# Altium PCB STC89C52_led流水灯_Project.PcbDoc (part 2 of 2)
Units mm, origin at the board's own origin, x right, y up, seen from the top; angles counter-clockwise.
Board outline 100 x 80 mm, 2 copper layers (Top Layer, Bottom Layer); 175 components, 183 nets, 540 pads, 112 vias.
Unrouted connection lines stored in the file: 28.
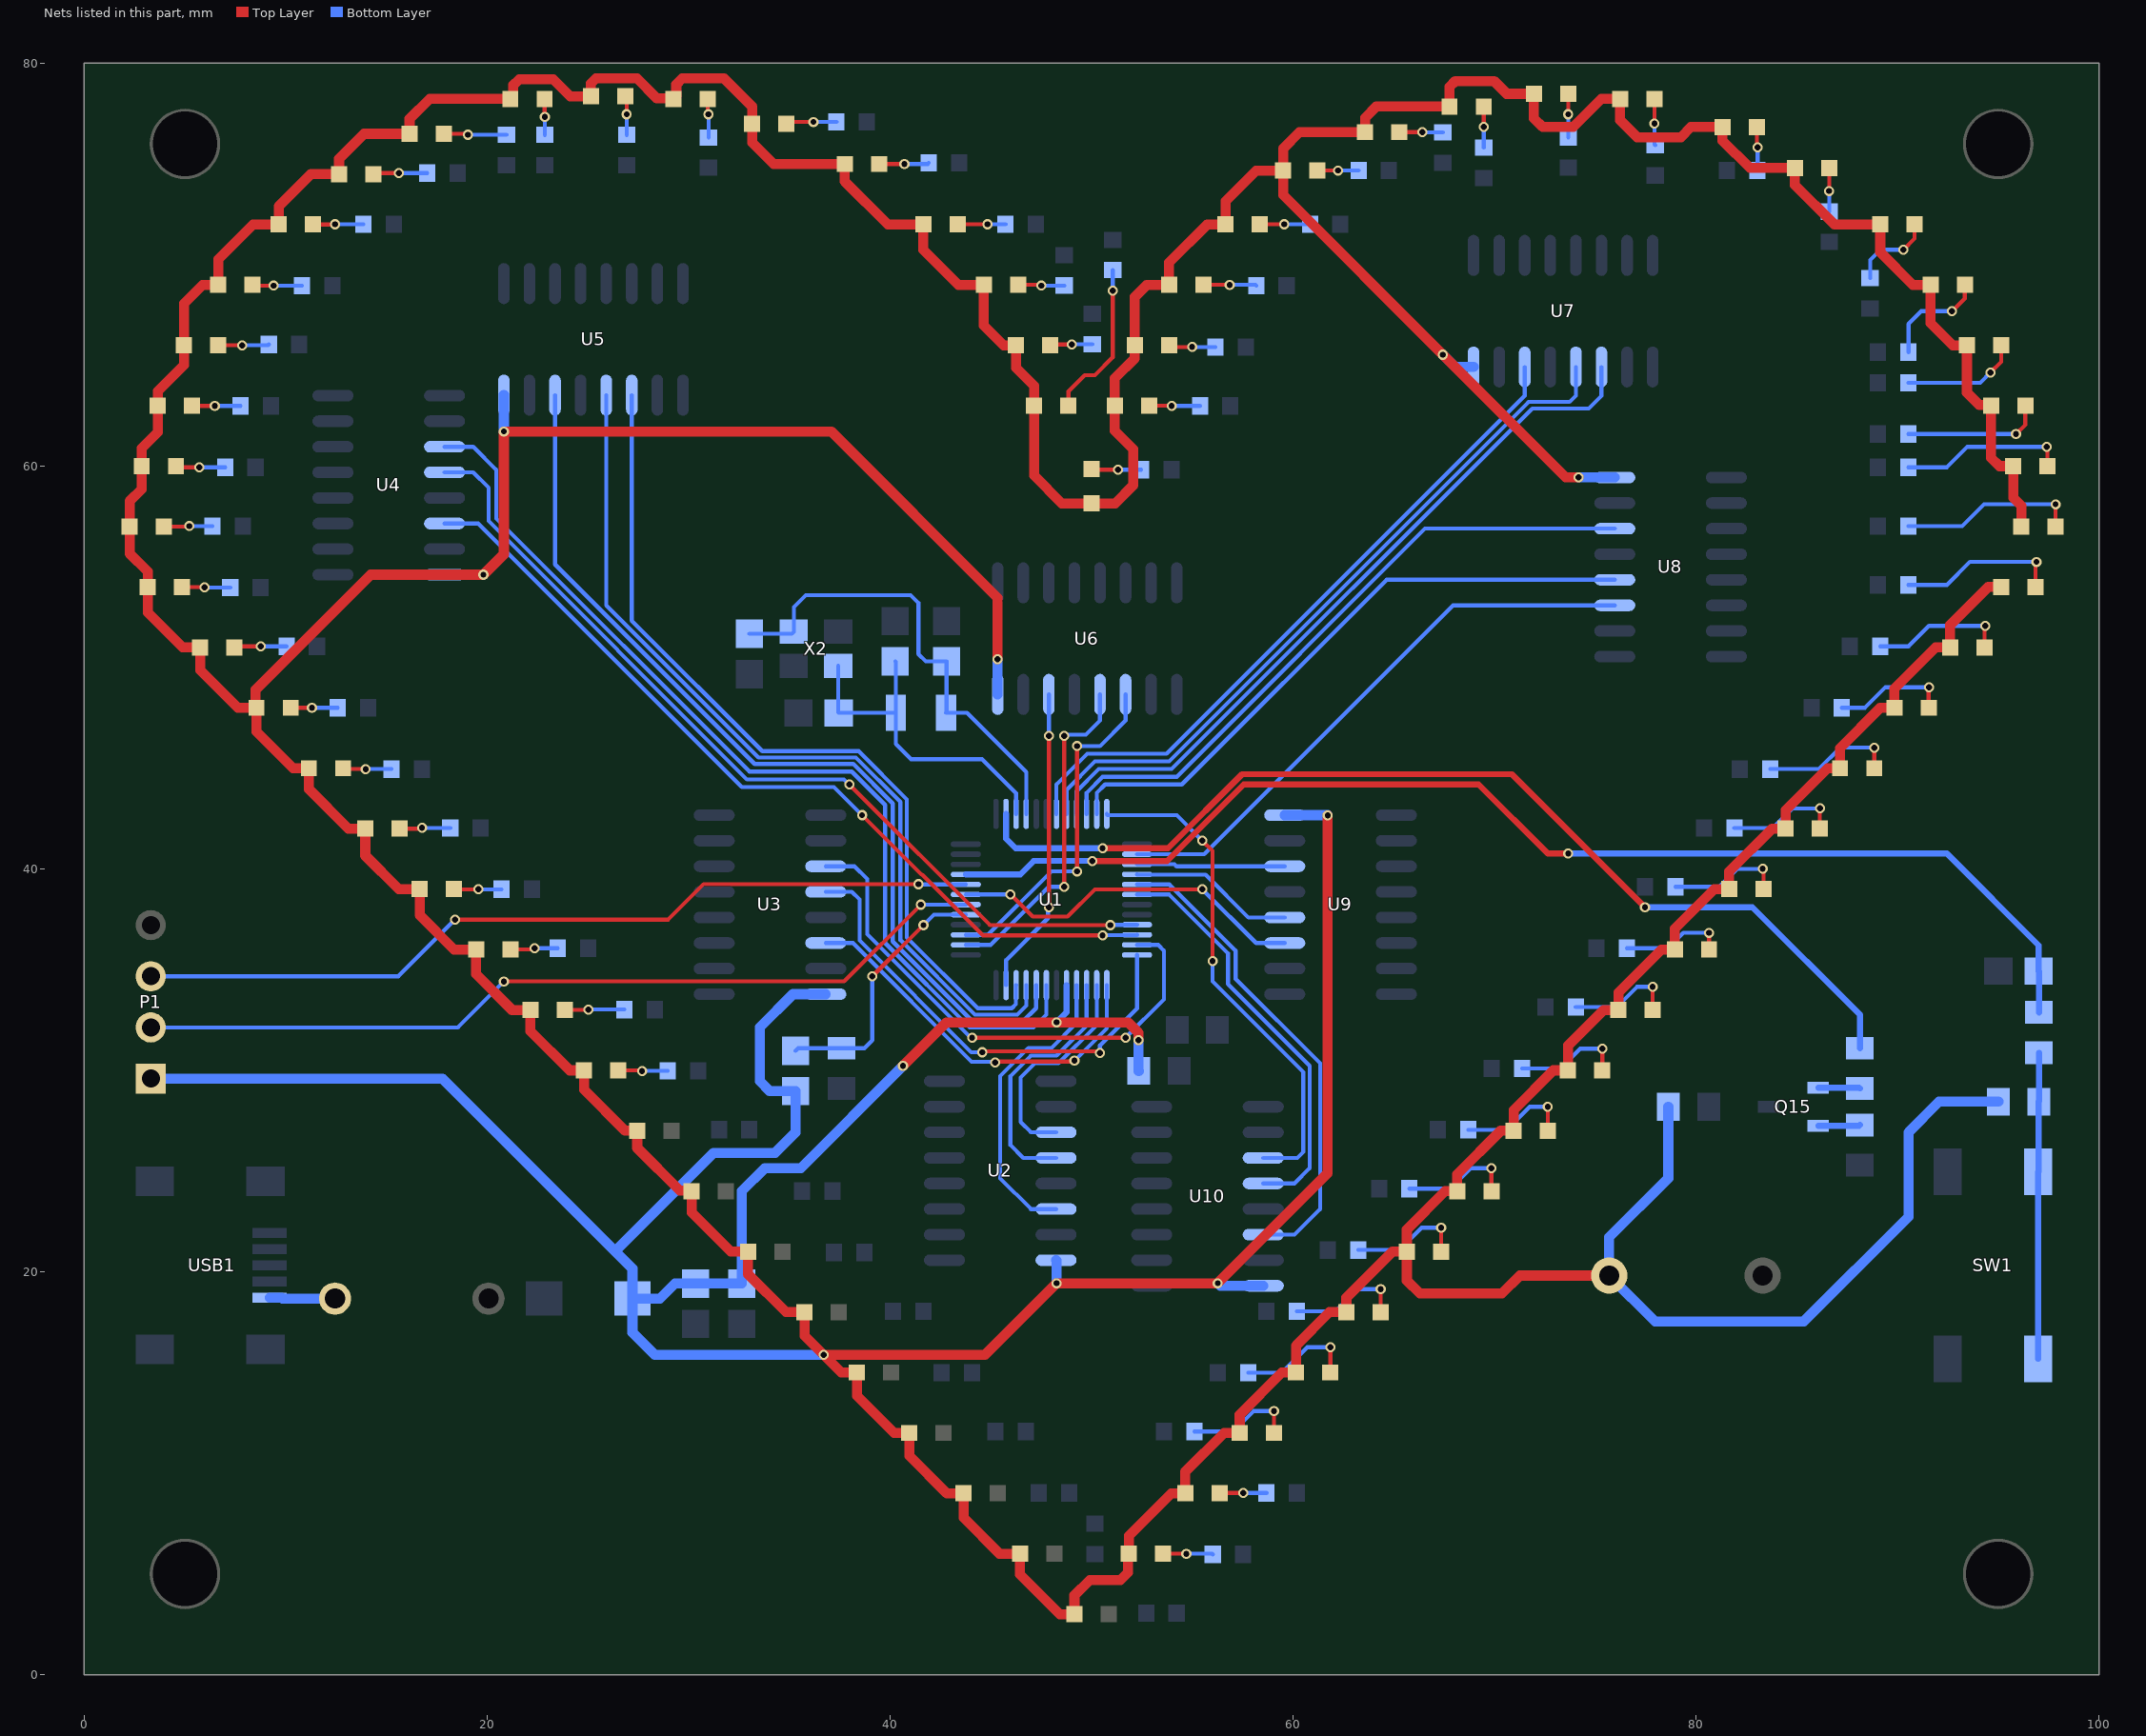
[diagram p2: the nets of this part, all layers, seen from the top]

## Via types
v1: diameter 0.5, hole 0.3, Top Layer to Bottom Layer, tented both sides, 112 vias

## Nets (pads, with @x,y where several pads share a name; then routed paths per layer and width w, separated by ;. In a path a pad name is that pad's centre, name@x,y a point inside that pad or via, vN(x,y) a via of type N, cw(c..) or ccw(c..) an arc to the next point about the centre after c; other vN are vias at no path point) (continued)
NetLED10_2: LED10.2 R10.2 | length 2.5
  Top Layer w0.2: LED10.2@26.505,30 27.658,30 v1(27.686,29.972)
  Bottom Layer w0.2: v1(27.686,29.972) R10.2@28.965,29.972
NetLED11_2: LED11.2 R11.2 | length 3
  Top Layer w0.2: LED11.2@23.851,33 24.999,33 v1(25.019,33.02)
  Bottom Layer w0.2: v1(25.019,33.02) R11.2@26.806,33.02
NetLED12_2: LED12.2 R12.2 | length 2.4
  Top Layer w0.2: LED12.2@21.151,36 22.293,36 v1(22.352,36.059)
  Bottom Layer w0.2: v1(22.352,36.059) 23.495,36.059 R12.2@23.504,36.068
NetLED13_2: LED13.2 R13.2 | length 2.4
  Top Layer w0.2: LED13.2@18.351,39 18.362,38.989 v1(19.558,38.989)
  Bottom Layer w0.2: v1(19.558,38.989) R13.2@20.71,38.989
NetLED14_2: LED14.2 R14.2 | length 2.5
  Top Layer w0.2: LED14.2@15.651,42 16.727,42 v1(16.764,42.037)
  Bottom Layer w0.2: v1(16.764,42.037) R14.2@18.17,42.037
NetLED15_2: LED15.2 R15.2 | length 2.4
  Top Layer w0.2: LED15.2@12.851,45 12.893,44.958 v1(13.97,44.958)
  Bottom Layer w0.2: v1(13.97,44.958) R15.2@15.249,44.958
NetLED16_2: LED16.2 R16.2 | length 2.3
  Top Layer w0.2: LED16.2@10.251,48 11.297,48 v1(11.303,48.006)
  Bottom Layer w0.2: v1(11.303,48.006) R16.2@12.582,48.006
NetLED17_2: LED17.2 R17.2 | length 2.6
  Top Layer w0.2: LED17.2@7.451,51 7.505,51.054 v1(8.763,51.054)
  Bottom Layer w0.2: v1(8.763,51.054) R17.2@10.042,51.054
NetLED18_2: LED18.2 R18.2 | length 2.4
  Top Layer w0.2: LED18.2@4.851,54 5.944,54 v1(5.969,53.975)
  Bottom Layer w0.2: v1(5.969,53.975) R18.2@7.248,53.975
NetLED19_2: LED19.2 R19.2 | length 2.4
  Top Layer w0.2: LED19.2@3.951,57 5.184,57 v1(5.207,57.023)
  Bottom Layer w0.2: v1(5.207,57.023) R19.2@6.359,57.023
NetLED20_2: LED20.2 R20.2 | length 2.5
  Top Layer w0.2: LED20.2@4.551,60 4.607,59.944 v1(5.715,59.944)
  Bottom Layer w0.2: v1(5.715,59.944) R20.2@6.994,59.944
NetLED21_2: LED21.2 R21.2 | length 2.4
  Top Layer w0.2: LED21.2@5.351,63 5.359,62.992 v1(6.477,62.992)
  Bottom Layer w0.2: v1(6.477,62.992) R21.2@7.756,62.992
NetLED22_2: LED22.2 R22.2 | length 2.5
  Top Layer w0.2: LED22.2@6.651,66 v1(7.834,66)
  Bottom Layer w0.2: v1(7.834,66) 9.121,66 R22.2@9.161,66.04
NetLED23_2: LED23.2 R23.2 | length 2.5
  Top Layer w0.2: LED23.2@8.351,69 8.39,68.961 v1(9.398,68.961)
  Bottom Layer w0.2: v1(9.398,68.961) R23.2@10.804,68.961
NetLED24_2: LED24.2 R24.2 | length 2.5
  Top Layer w0.2: LED24.2@11.351,72 12.437,72 v1(12.446,72.009)
  Bottom Layer w0.2: v1(12.446,72.009) R24.2@13.852,72.009
NetLED25_2: LED25.2 R25.2 | length 2.7
  Top Layer w0.2: LED25.2@14.351,74.5 14.4,74.549 v1(15.621,74.549)
  Bottom Layer w0.2: v1(15.621,74.549) R25.2@17.027,74.549
NetLED26_2: LED26.2 R26.2 | length 3.1
  Top Layer w0.2: LED26.2@17.851,76.5 19.004,76.5 v1(19.05,76.454)
  Bottom Layer w0.2: v1(19.05,76.454) R26.2@20.955,76.454
NetLED27_2: LED27.2 R27.2 | length 1.8
  Top Layer w0.2: LED27.2@22.851,78.232 22.851,77.352 v1(22.86,77.343)
  Bottom Layer w0.2: R27.2@22.86,76.445 v1(22.86,77.343)
NetLED28_2: LED28.2 R28.2 | length 1.9
  Top Layer w0.2: LED28.2@26.851,78.359 26.924,78.286 v1(26.924,77.47)
  Bottom Layer w0.2: R28.2@26.924,76.445 v1(26.924,77.47)
NetLED29_2: LED29.2 R29.2 | length 1.9
  Top Layer w0.2: LED29.2@30.95,78.232 30.95,77.508 v1(30.988,77.47)
  Bottom Layer w0.2: R29.2@30.988,76.318 v1(30.988,77.47)
NetLED30_2: LED30.2 R30.2 | length 2.5
  Top Layer w0.2: LED30.2@34.851,77 34.94,77.089 v1(36.195,77.089)
  Bottom Layer w0.2: v1(36.195,77.089) R30.2@37.338,77.089
NetLED31_2: LED31.2 R31.2 | length 2.5
  Top Layer w0.2: LED31.2@39.451,75 v1(40.71,75)
  Bottom Layer w0.2: v1(40.71,75) 41.862,75 R31.2@41.919,75.057
NetLED32_2: LED32.2 R32.2 | length 2.4
  Top Layer w0.2: LED32.2@43.351,72 43.36,72.009 v1(44.831,72.009)
  Bottom Layer w0.2: v1(44.831,72.009) R32.2@45.729,72.009
NetLED33_2: LED33.2 R33.2 | length 2.3
  Top Layer w0.2: LED33.2@46.351,69 47.459,69 v1(47.498,68.961)
  Bottom Layer w0.2: v1(47.498,68.961) R33.2@48.65,68.961
NetLED34_2: LED34.2 R34.2 | length 2.1
  Top Layer w0.2: LED34.2@47.951,66 47.991,66.04 v1(49.022,66.04)
  Bottom Layer w0.2: v1(49.022,66.04) 49.031,66.049 R34.2@50.038,66.049
NetLED35_2: LED35.2 R35.2 | length 7.9
  Top Layer w0.2: LED35.2@48.851,63 48.851,63.71 49.657,64.516 50.165,64.516 51.054,65.405 v1(51.054,68.707)
  Bottom Layer w0.2: v1(51.054,68.707) R35.2@51.054,69.732
NetLED36_2: LED36.2 R36.2 | length 2.5
  Top Layer w0.2: LED36.2@50,59.851 50.034,59.817 v1(51.308,59.817)
  Bottom Layer w0.2: v1(51.308,59.817) R36.2@52.46,59.817
NetLED37_2: LED37.2 R37.2 | length 2.5
  Top Layer w0.2: LED37.2@52.851,63 53.967,63 v1(53.975,62.992)
  Bottom Layer w0.2: v1(53.975,62.992) R37.2@55.381,62.992
NetLED38_2: LED38.2 R38.2 | length 2.3
  Top Layer w0.2: LED38.2@53.851,66 53.938,65.913 v1(54.991,65.913)
  Bottom Layer w0.2: v1(54.991,65.913) R38.2@56.143,65.913
NetLED39_2: LED39.2 R39.2 | length 2.6
  Top Layer w0.2: LED39.2@55.551,69 v1(56.857,69)
  Bottom Layer w0.2: v1(56.857,69) 58.136,69 R39.2@58.175,68.961
NetLED40_2: LED40.2 R40.2 | length 2.5
  Top Layer w0.2: LED40.2@58.351,72 58.36,72.009 v1(59.563,72.009)
  Bottom Layer w0.2: v1(59.563,72.009) R40.2@60.842,72.009
NetLED41_2: LED41.2 R41.2 | length 2
  Top Layer w0.2: LED41.2@61.214,74.676 v1(62.23,74.676)
  Bottom Layer w0.2: v1(62.23,74.676) R41.2@63.255,74.676
NetLED42_2: LED42.2 R42.2 | length 2.2
  Top Layer w0.2: LED42.2@65.278,76.581 v1(66.421,76.581)
  Bottom Layer w0.2: v1(66.421,76.581) 66.43,76.572 R42.2@67.437,76.572
NetLED43_2: LED43.2 R43.2 | length 2
  Top Layer w0.2: v1(69.469,76.835) LED43.2@69.469,77.851
  Bottom Layer w0.2: R43.2@69.469,75.81 v1(69.469,76.835)
NetLED44_2: LED44.2 R44.2 | length 2.2
  Top Layer w0.2: v1(73.66,77.47) LED44.2@73.66,78.486
  Bottom Layer w0.2: R44.2@73.66,76.318 v1(73.66,77.47)
NetLED45_2: LED45.2 R45.2 | length 2.3
  Top Layer w0.2: v1(77.94,77) LED45.2@77.94,78.232
  Bottom Layer w0.2: v1(77.94,77) 77.94,75.975 R45.2@77.978,75.937
NetLED46_2: LED46.2 R46.2 | length 2.2
  Top Layer w0.2: LED46.2@83.02,76.835 83.02,75.857 v1(83.058,75.819)
  Bottom Layer w0.2: R46.2@83.049,74.676 83.058,74.685 v1(83.058,75.819)
NetLED47_2: LED47.2 R47.2 | length 2.2
  Top Layer w0.2: v1(86.614,73.66) LED47.2@86.614,74.803
  Bottom Layer w0.2: R47.2@86.614,72.635 v1(86.614,73.66)
NetLED48_2: LED48.2 R48.2 | length 4.2
  Top Layer w0.2: v1(90.297,70.739) 90.851,71.293 LED48.2@90.851,72
  Bottom Layer w0.2: R48.2@88.646,69.333 88.646,70.231 89.154,70.739 v1(90.297,70.739)
NetLED49_2: LED49.2 R49.2 | length 5.4
  Top Layer w0.2: v1(92.71,67.691) 93.345,68.326 93.345,68.994 LED49.2@93.351,69
  Bottom Layer w0.2: R49.2@90.551,65.659 90.551,67.056 91.186,67.691 v1(92.71,67.691)
NetLED50_2: LED50.2 R50.2 | length 5.9
  Top Layer w0.2: v1(94.615,64.643) 95.151,65.179 LED50.2@95.151,66
  Bottom Layer w0.2: R50.2@90.542,64.135 94.107,64.135 v1(94.615,64.643)
NetLED51_2: LED51.2 R51.2 | length 6.9
  Top Layer w0.2: v1(95.885,61.595) 96.351,62.061 LED51.2@96.351,63
  Bottom Layer w0.2: R51.2@90.542,61.595 v1(95.885,61.595)
NetLED52_2: LED52.2 R52.2 | length 8.3
  Top Layer w0.2: v1(97.409,60.96) 97.409,60.833 97.451,60.791 LED52.2@97.451,60
  Bottom Layer w0.2: R52.2@90.542,59.944 92.456,59.944 93.472,60.96 v1(97.409,60.96)
NetLED53_2: LED53.2 R53.2 | length 8.9
  Top Layer w0.2: LED53.2@97.851,57 v1(97.851,58.105)
  Bottom Layer w0.2: R53.2@90.542,57.023 93.218,57.023 94.3,58.105 v1(97.851,58.105)
NetLED54_2: LED54.2 R54.2 | length 8.1
  Top Layer w0.2: LED54.2@96.851,54 96.851,55.195 v1(96.901,55.245)
  Bottom Layer w0.2: R54.2@90.542,54.102 92.456,54.102 93.599,55.245 v1(96.901,55.245)
NetLED55_2: LED55.2 R55.2 | length 6.7
  Top Layer w0.2: LED55.2@94.323,51 94.323,52.032 v1(94.361,52.07)
  Bottom Layer w0.2: R55.2@89.145,51.054 90.551,51.054 91.567,52.07 v1(94.361,52.07)
NetLED56_2: LED56.2 R56.2 | length 5.8
  Top Layer w0.2: LED56.2@91.551,48 91.551,49.006 v1(91.567,49.022)
  Bottom Layer w0.2: R56.2@87.24,48.006 88.392,48.006 89.408,49.022 v1(91.567,49.022)
NetLED57_2: LED57.2 R57.2 | length 6.6
  Top Layer w0.2: LED57.2@88.851,45 v1(88.851,46.023)
  Bottom Layer w0.2: R57.2@83.684,44.958 86.106,44.958 87.171,46.023 v1(88.851,46.023)
NetLED58_2: LED58.2 R58.2 | length 5.7
  Top Layer w0.2: LED58.2@86.151,42 v1(86.151,43.008)
  Bottom Layer w0.2: R58.2@81.906,42.037 83.82,42.037 84.791,43.008 v1(86.151,43.008)
NetLED59_2: LED59.2 R59.2 | length 5.7
  Top Layer w0.2: v1(83.312,40.005) 83.351,39.966 LED59.2@83.351,39
  Bottom Layer w0.2: R59.2@78.985,39.116 81.153,39.116 82.042,40.005 v1(83.312,40.005)
NetLED60_2: LED60.2 R60.2 | length 5.2
  Top Layer w0.2: v1(80.645,36.83) 80.651,36.824 LED60.2@80.651,36
  Bottom Layer w0.2: R60.2@76.572,36.068 78.613,36.068 79.375,36.83 v1(80.645,36.83)
NetLED61_2: LED61.2 R61.2 | length 5.4
  Top Layer w0.2: LED61.2@77.851,33 v1(77.851,34.145)
  Bottom Layer w0.2: R61.2@74.032,33.147 76.073,33.147 77.071,34.145 v1(77.851,34.145)
NetLED62_2: LED62.2 R62.2 | length 5.5
  Top Layer w0.2: LED62.2@75.351,30 v1(75.351,31.075)
  Bottom Layer w0.2: R62.2@71.365,30.099 73.279,30.099 74.255,31.075 v1(75.351,31.075)
NetLED63_2: LED63.2 R63.2 | length 5.6
  Top Layer w0.2: v1(72.644,28.194) 72.651,28.187 LED63.2@72.651,27
  Bottom Layer w0.2: R63.2@68.698,27.051 70.612,27.051 71.755,28.194 v1(72.644,28.194)
NetLED64_2: LED64.2 R64.2 | length 5.6
  Top Layer w0.2: v1(69.85,25.146) v1(69.85,25.146) LED64.2@69.851,24
  Bottom Layer w0.2: R64.2@65.777,24.13 67.818,24.13 68.834,25.146 v1(69.85,25.146)
NetLED65_2: LED65.2 R65.2 | length 5.8
  Top Layer w0.2: LED65.2@67.351,21 v1(67.351,22.184)
  Bottom Layer w0.2: R65.2@63.237,21.082 65.278,21.082 66.38,22.184 v1(67.351,22.184)
NetLED66_2: LED66.2 R66.2 | length 5.8
  Top Layer w0.2: LED66.2@64.351,18 v1(64.351,19.139)
  Bottom Layer w0.2: R66.2@60.189,18.034 62.103,18.034 63.208,19.139 v1(64.351,19.139)
NetLED67_2: LED67.2 R67.2 | length 5.9
  Top Layer w0.2: v1(61.849,16.256) 61.851,16.254 LED67.2@61.851,15
  Bottom Layer w0.2: R67.2@57.776,14.986 59.436,14.986 60.706,16.256 v1(61.849,16.256)
NetLED68_2: LED68.2 R68.2 | length 5.4
  Top Layer w0.2: LED68.2@59.055,12 v1(59.055,13.081)
  Bottom Layer w0.2: R68.2@55.109,12.065 57.023,12.065 58.039,13.081 v1(59.055,13.081)
NetLED69_2: LED69.2 R69.2 | length 2.3
  Top Layer w0.2: LED69.2@56.351,9 56.368,9.017 v1(57.531,9.017)
  Bottom Layer w0.2: v1(57.531,9.017) R69.2@58.683,9.017
NetLED70_2: LED70.2 R70.2 | length 2.5
  Top Layer w0.2: LED70.2@53.551,6 v1(54.706,6)
  Bottom Layer w0.2: v1(54.706,6) 55.985,6 R70.2@56.016,5.969
NetQ15_1: Q15.1 R75.1 | length 2.1
  Bottom Layer w0.3: Q15.1@86.071,29.144 88.093,29.144 R75.1@88.138,29.099
NetQ15_2: Q15.2 R72.2 | length 2.1
  Bottom Layer w0.3: Q15.2@86.071,27.244 88.093,27.244 R72.2@88.138,27.289
NetR73_1: R73.1 R74.1 SW1.1 SW1.2 | length 15.2
  Bottom Layer w0.3: SW1.1@96.992,15.677 SW1.2@96.992,24.963 97.012,24.983 R73.1@97.012,28.448 97.028,28.464 R74.1@97.028,30.877
P0.0: U1.40 U2.14 | length 15.2
  Bottom Layer w0.2: U2.14@48.235,23.114 46.99,23.114 45.466,24.638 45.466,29.718 46.863,31.115 48.006,31.115 49.256,32.365 U1.40@49.256,34.231
P0.1: U1.39 U2.12 | length 12.8
  Bottom Layer w0.2: U2.12@48.235,25.654 46.609,25.654 45.974,26.289 45.974,29.718 46.99,30.734 48.26,30.734 49.756,32.23 U1.39@49.756,34.231
P0.2: U1.38 U2.11 | length 11
  Bottom Layer w0.2: U2.11@48.235,26.924 46.99,26.924 46.482,27.432 46.482,29.651 47.184,30.353 48.357,30.353 50.256,32.252 U1.38@50.256,34.231
P0.3: U1.37 U3.14 | length 19.3
  Top Layer w0.2: v1(45.212,30.391) 45.257,30.436 49.105,30.436 v1(49.149,30.48)
  Bottom Layer w0.2: U3.14@36.805,36.322 38.155,36.322 44.048,30.429 45.174,30.429 v1(45.212,30.391) ; v1(49.149,30.48) 50.756,32.087 U1.37@50.756,34.231
P0.4: U1.36 U3.12 | length 23.8
  Top Layer w0.2: v1(44.577,30.899) 44.628,30.95 50.249,30.95 50.338,30.861 v1(50.419,30.861)
  Bottom Layer w0.2: U3.12@36.805,38.862 38.1,38.862 38.481,38.481 38.481,36.449 44.027,30.903 44.573,30.903 v1(44.577,30.899) ; v1(50.419,30.861) 50.419,31.242 52.256,33.079 U1.36@52.256,35.731
P0.5: U1.35 U3.11 | length 26.6
  Top Layer w0.2: v1(44.069,31.623) v1(51.689,31.623)
  Bottom Layer w0.2: U3.11@36.805,40.132 38.227,40.132 38.862,39.497 38.862,36.758 43.997,31.623 v1(44.069,31.623) ; v1(51.689,31.623) 53.594,33.528 53.594,35.941 53.304,36.231 U1.35@52.256,36.231
P0.6: U1.34 U4.14 | length 42.9
  Top Layer w0.2: v1(38.608,42.672) 41.567,39.713 41.597,39.713 44.607,36.703 v1(50.546,36.703)
  Bottom Layer w0.2: U4.14@17.882,57.15 19.558,57.15 32.639,44.069 37.211,44.069 v1(38.608,42.672) ; v1(50.546,36.703) 50.561,36.718 52.243,36.718 U1.34@52.256,36.731
P0.7: U1.33 U4.12 | length 44.7
  Top Layer w0.2: v1(37.973,44.196) 44.958,37.211 v1(50.927,37.211)
  Bottom Layer w0.2: U4.12@17.882,59.69 19.304,59.69 20.066,58.928 20.066,57.277 32.893,44.45 37.706,44.45 37.96,44.196 v1(37.973,44.196) ; v1(50.927,37.211) 50.937,37.221 52.246,37.221 U1.33@52.256,37.231
P1.0: U1.43 U4.11 | length 49
  Bottom Layer w0.2: U4.11@17.882,60.96 19.304,60.96 20.447,59.817 20.447,57.404 33.02,44.831 38.1,44.831 39.751,43.18 39.751,36.322 43.947,32.126 47.122,32.126 47.756,32.76 U1.43@47.756,34.231
P1.1: U1.44 U5.14 | length 47.1
  Bottom Layer w0.2: U5.14@23.368,63.525 23.368,55.118 33.274,45.212 38.172,45.212 40.132,43.252 40.132,36.394 44.08,32.446 46.604,32.446 47.244,33.086 47.244,34.219 U1.44@47.256,34.231
P1.2: U1.45 U5.12 | length 44.9
  Bottom Layer w0.2: U5.12@25.908,63.525 25.908,53.086 33.462,45.532 38.304,45.532 40.513,43.323 40.513,36.465 44.212,32.766 46.306,32.766 46.756,33.216 U1.45@46.756,34.231
P1.3: U1.46 U5.11 | length 43.3
  Bottom Layer w0.2: U5.11@27.178,63.525 27.178,52.324 33.65,45.852 38.437,45.852 40.833,43.456 40.833,36.598 44.345,33.086 46.04,33.086 46.243,33.289 46.243,34.218 U1.46@46.256,34.231
P1.4: U1.47 U6.14 | length 15.3
  Top Layer w0.2: v1(47.879,38.1) v1(47.879,46.609)
  Bottom Layer w0.2: U1.47@45.756,34.231 45.756,35.469 47.837,37.55 47.837,38.058 v1(47.879,38.1) ; v1(47.879,46.609) U6.14@47.879,48.666
P1.5: U1.2 U6.12 | length 17
  Top Layer w0.2: v1(48.641,39.116) v1(48.641,46.609)
  Bottom Layer w0.2: U1.2@43.756,36.231 44.994,36.231 47.879,39.116 v1(48.641,39.116) ; v1(48.641,46.609) 48.698,46.666 49.714,46.666 50.419,47.371 U6.12@50.419,48.666
P1.6: U1.3 U6.11 | length 17.3
  Top Layer w0.2: v1(49.276,39.878) v1(49.276,46.101)
  Bottom Layer w0.2: U1.3@43.756,36.731 44.859,36.731 48.006,39.878 v1(49.276,39.878) ; v1(49.276,46.101) 50.419,46.101 51.689,47.371 U6.11@51.689,48.666
P2.0: U1.19 U7.14 | length 34.1
  Bottom Layer w0.2: U1.19@48.256,42.731 48.256,44.192 49.784,45.72 53.721,45.72 71.501,63.5 U7.14@71.501,64.922
P2.1: U1.20 U7.12 | length 36
  Bottom Layer w0.2: U1.20@48.756,42.731 48.756,43.93 50.165,45.339 53.848,45.339 71.694,63.185 73.726,63.185 74.041,63.5 U7.12@74.041,64.922
P2.2: U1.21 U7.11 | length 36.7
  Bottom Layer w0.2: U1.21@49.256,42.731 49.256,43.856 50.358,44.958 53.975,44.958 71.882,62.865 74.676,62.865 75.311,63.5 U7.11@75.311,64.922
P2.3: U1.22 U8.14 | length 32.7
  Bottom Layer w0.2: U1.22@49.756,42.731 49.756,43.787 50.546,44.577 54.229,44.577 66.548,56.896 U8.14@75.971,56.896
P2.4: U1.23 U8.12 | length 31.1
  Bottom Layer w0.2: U1.23@50.256,42.731 50.256,43.779 50.673,44.196 54.483,44.196 64.643,54.356 U8.12@75.971,54.356
P2.5: U1.26 U8.11 | length 28.8
  Bottom Layer w0.2: U1.26@52.256,40.731 55.59,40.731 67.945,53.086 U8.11@75.971,53.086
P2.6: U1.27 U9.14 | length 7.4
  Bottom Layer w0.2: U1.27@52.256,40.231 54.119,40.231 54.218,40.132 U9.14@59.588,40.132
P2.7: U1.28 U9.12 | length 8.2
  Bottom Layer w0.2: U1.28@52.256,39.731 52.269,39.718 55.659,39.718 57.785,37.592 U9.12@59.588,37.592
P3.0: P1.2 U1.6 | length 43
  Top Layer w0.2: v1(20.828,34.417) 37.719,34.417 v1(41.529,38.227)
  Bottom Layer w0.2: P1.2@3.302,32.131 18.542,32.131 v1(20.828,34.417) ; v1(41.529,38.227) 41.533,38.231 U1.6@43.756,38.231
P3.1: P1.3 U1.8 | length 42.4
  Top Layer w0.2: v1(18.403,37.487) 28.984,37.487 30.74,39.243 v1(41.402,39.243)
  Bottom Layer w0.2: P1.3@3.302,34.671 15.587,34.671 v1(18.403,37.487) ; v1(41.402,39.243) 41.414,39.231 U1.8@43.756,39.231
P3.2: C5.2 R74.2 U1.9 | length 61.8
  Top Layer w0.3: v1(50.038,40.386) 53.748,40.386 57.558,44.196 69.215,44.196 72.644,40.767 v1(73.66,40.767)
  Bottom Layer w0.3: U1.9@43.756,39.731 46.462,39.731 47.129,40.398 50.026,40.398 v1(50.038,40.386) ; v1(73.66,40.767) 92.456,40.767 97.012,36.211 C5.2@97.012,34.925 97.028,34.909 R74.2@97.028,32.877
P3.7: R75.2 U1.14 | length 52
  Top Layer w0.3: v1(50.546,41.021) 53.789,41.021 57.472,44.704 70.866,44.704 v1(77.47,38.1)
  Bottom Layer w0.3: U1.14@45.756,42.731 45.756,41.493 46.228,41.021 v1(50.546,41.021) ; v1(77.47,38.1) 82.804,38.1 88.138,32.766 R75.2@88.138,31.099
P4.3: U1.7 U9.11 | length 18
  Top Layer w0.2: v1(45.974,38.735) 47.079,37.63 48.806,37.63 50.165,38.989 v1(55.499,38.989)
  Bottom Layer w0.2: U1.7@43.756,38.731 43.758,38.733 45.972,38.733 v1(45.974,38.735) ; v1(55.499,38.989) 58.166,36.322 U9.11@59.588,36.322
P4.4: U1.29 U10.14 | length 24.2
  Bottom Layer w0.2: U1.29@52.256,39.231 53.86,39.231 57.15,35.941 57.15,34.544 61.341,30.353 61.341,23.114 60.071,21.844 U10.14@58.522,21.844
P4.5: U1.30 U10.12 | length 20.7
  Bottom Layer w0.2: U1.30@52.256,38.731 53.852,38.731 56.769,35.814 56.769,34.29 60.833,30.226 60.833,25.146 60.071,24.384 U10.12@58.522,24.384
P5.0: U1.24 U10.11 | length 24.9
  Top Layer w0.2: v1(55.499,41.402) 56.007,40.894 56.007,35.924 v1(56.007,35.433)
  Bottom Layer w0.2: U1.24@50.756,42.731 50.788,42.699 50.788,42.672 54.229,42.672 v1(55.499,41.402) ; v1(56.007,35.433) 56.007,34.417 60.513,29.911 60.513,25.959 60.208,25.654 U10.11@58.522,25.654
RST: C6.1 R71.2 U1.5 | length 13.1
  Top Layer w0.2: v1(39.116,34.671) v1(41.656,37.211)
  Bottom Layer w0.2: C6.1@35.306,30.972 35.433,31.099 R71.2@37.592,31.099 38.719,31.099 39.116,31.496 v1(39.116,34.671) ; v1(41.656,37.211) 42.176,37.731 U1.5@43.756,37.731
VBUS: SW2.1 USB1.1 | length 3.3
  Bottom Layer w0.5: USB1.1@9.2,18.72 9.8,18.72 9.851,18.669 SW2.1@12.446,18.669
VCC_5V: BUZZER2.1 C3.2 C4.2 C6.2 D1.1 LED1.1 LED2.1 LED3.1 LED4.1 LED5.1 LED6.1 LED7.1 LED8.1 LED9.1 LED10.1 LED11.1 LED12.1 LED13.1 LED14.1 LED15.1 LED16.1 LED17.1 LED18.1 LED19.1 LED20.1 LED21.1 LED22.1 LED23.1 LED24.1 LED25.1 LED26.1 LED27.1 LED28.1 LED29.1 LED30.1 LED31.1 LED32.1 LED33.1 LED34.1 LED35.1 LED36.1 LED37.1 LED38.1 LED39.1 LED40.1 LED41.1 LED42.1 LED43.1 LED44.1 LED45.1 LED46.1 LED47.1 LED48.1 LED49.1 LED50.1 LED51.1 LED52.1 LED53.1 LED54.1 LED55.1 LED56.1 LED57.1 LED58.1 LED59.1 LED60.1 LED61.1 LED62.1 LED63.1 LED64.1 LED65.1 LED66.1 LED67.1 LED68.1 LED69.1 LED70.1 P1.1 R73.2 R76.2 R78.2 U1.41 U2.16 U3.16 U4.16 U5.16 U6.16 U7.16 U8.16 U9.16 U10.16 | length 610.1
  Top Layer w0.5: v1(40.64,30.226) 42.799,32.385 v1(48.26,32.385) 51.804,32.385 52.324,31.865 v1(52.324,31.496) ; v1(45.339,50.419) 45.339,53.467 37.084,61.722 v1(20.828,61.722) 20.828,55.626 v1(19.812,54.61) 14.224,54.61 8.509,48.895 8.509,48.04 LED16.1@8.549,48 ; v1(61.722,42.66) 61.722,24.892 v1(56.261,19.431) v1(48.26,19.431) 44.704,15.875 v1(36.703,15.875) ; v1(74.168,59.436) 73.533,59.436 v1(67.437,65.532) 59.512,73.457 LED41.1@59.512,74.676 ; BUZZER2.1@75.692,19.812 71.262,19.812 70.373,18.923 66.294,18.923 65.649,19.568 LED65.1@65.649,21 ; LED54.1@95.149,54 94.513,54 92.621,52.108 LED55.1@92.621,51 91.894,51 89.849,48.955 LED56.1@89.849,48 89.148,48 87.149,46.001 LED57.1@87.149,45 86.529,45 84.449,42.92 LED58.1@84.449,42 83.783,42 81.649,39.866 LED59.1@81.649,39 80.91,39 78.949,37.039 LED60.1@78.949,36 78.291,36 76.149,33.858 LED61.1@76.149,33 75.418,33 73.649,31.231 LED62.1@73.649,30 72.926,30 70.949,28.023 LED63.1@70.949,27 70.307,27 68.149,24.842 LED64.1@68.149,24 67.561,24 65.649,22.088 LED65.1@65.649,21 ; LED53.1@96.149,57 96.149,58.029 95.749,58.429 LED52.1@95.749,60 95.067,60 94.649,60.418 LED51.1@94.649,63 94.616,63.033 94.066,63.033 93.449,63.65 LED50.1@93.449,66 92.75,66 91.649,67.101 LED49.1@91.649,69 90.766,69 89.149,70.617 LED48.1@89.149,72 86.877,72 84.912,73.965 LED47.1@84.912,74.803 82.677,74.803 81.318,76.162 LED46.1@81.318,76.835 79.756,76.835 79.248,76.327 77.089,76.327 76.238,77.178 LED45.1@76.238,78.232 75.311,78.232 73.914,76.835 72.39,76.835 71.958,77.267 LED44.1@71.958,78.486 70.612,78.486 69.977,79.121 68.06,79.121 67.767,78.828 LED43.1@67.767,77.851 64.135,77.851 63.576,77.292 LED42.1@63.576,76.581 60.325,76.581 59.512,75.768 LED41.1@59.512,74.676 ; LED16.1@8.549,48 7.626,48 5.749,49.877 LED17.1@5.749,51 4.88,51 3.149,52.731 LED18.1@3.149,54 3.149,54.763 2.249,55.663 LED19.1@2.249,57 2.249,58.256 2.849,58.856 LED20.1@2.849,60 2.849,60.888 3.649,61.688 LED21.1@3.649,63 3.649,63.72 4.949,65.02 LED22.1@4.949,66 4.949,68.068 5.881,69 LED23.1@6.649,69 6.649,70.276 8.373,72 LED24.1@9.649,72 9.649,72.895 11.254,74.5 LED25.1@12.649,74.5 12.649,75.26 13.889,76.5 LED26.1@16.149,76.5 16.149,77.236 17.145,78.232 LED27.1@21.149,78.232 21.299,78.382 21.299,78.916 21.592,79.209 23.28,79.209 24.13,78.359 LED28.1@25.149,78.359 25.149,78.991 25.406,79.248 27.432,79.248 28.418,78.262 29.218,78.262 LED29.1@29.248,78.232 29.386,78.37 29.386,78.955 29.679,79.248 31.75,79.248 33.149,77.849 LED30.1@33.149,77 33.149,76.071 34.22,75 LED31.1@37.749,75 37.749,74.138 39.887,72 LED32.1@41.649,72 41.649,70.746 43.395,69 LED33.1@44.649,69 44.649,66.984 45.633,66 LED34.1@46.249,66 46.249,64.876 47.149,63.976 LED35.1@47.149,63 47.149,59.531 48.531,58.149 LED36.1@50,58.149 51.164,58.149 52.07,59.055 52.07,60.833 51.149,61.754 LED37.1@51.149,63 51.149,64.357 52.149,65.357 LED38.1@52.149,66 52.149,68.405 52.744,69 LED39.1@53.849,69 53.849,70.105 55.744,72 LED40.1@56.649,72 56.649,73.159 58.166,74.676 LED41.1@59.512,74.676 ; LED16.1@8.549,48 8.549,46.823 10.372,45 LED15.1@11.149,45 11.149,43.969 13.118,42 LED14.1@13.949,42 13.949,40.661 15.61,39 LED13.1@16.649,39 16.649,37.707 18.356,36 LED12.1@19.449,36 19.449,34.78 21.229,33 LED11.1@22.149,33 22.149,31.953 24.102,30 LED10.1@24.803,30 24.803,29.045 26.848,27 LED9.1@27.449,27 27.449,26.145 29.566,24.028 30.121,24.028 LED8.1@30.149,24 30.149,22.937 32.086,21 LED7.1@32.949,21 32.949,19.883 34.832,18 LED6.1@35.749,18 35.749,16.829 v1(36.703,15.875) ; v1(36.703,15.875) 37.578,15 LED5.1@38.349,15 38.349,13.848 40.197,12 LED4.1@40.949,12 40.949,10.867 42.816,9 LED3.1@43.649,9 43.649,7.786 45.435,6 LED2.1@46.449,6 46.449,4.986 48.435,3 LED1.1@49.149,3 49.149,3.937 49.911,4.699 51.435,4.699 51.816,5.08 51.816,5.967 LED70.1@51.849,6 51.849,6.891 53.958,9 LED69.1@54.649,9 54.649,10.072 56.577,12 LED68.1@57.353,12 57.353,12.903 59.45,15 LED67.1@60.149,15 60.149,16.334 61.815,18 LED66.1@62.649,18 62.649,18.707 64.942,21 LED65.1@65.649,21
  Bottom Layer w0.3: v1(48.26,32.385) 48.756,32.881 U1.41@48.756,34.231
  Bottom Layer w0.5: P1.1@3.302,29.591 17.78,29.591 26.352,21.018 ; U4.16@17.882,54.61 v1(19.812,54.61) ; v1(20.828,61.722) U5.16@20.828,63.525 ; v1(36.703,15.875) 28.321,15.875 27.211,16.985 D1.1@27.211,18.669 ; U3.16@36.805,33.782 35.179,33.782 33.528,32.131 33.528,29.464 34.02,28.972 C6.2@35.306,28.972 35.306,26.924 34.29,25.908 31.242,25.908 26.352,21.018 ; v1(40.64,30.226) 35.56,25.146 33.782,25.146 32.639,24.003 C4.2@32.639,19.415 C3.2@30.353,19.415 29.321,19.415 28.575,18.669 D1.1@27.211,18.669 ; U6.16@45.339,48.666 v1(45.339,50.419) ; U2.16@48.235,20.574 48.26,20.549 v1(48.26,19.431) ; v1(52.324,31.496) 52.324,29.988 R78.2@52.34,29.972 ; v1(56.261,19.431) 56.388,19.304 U10.16@58.522,19.304 ; U9.16@59.588,42.672 61.71,42.672 v1(61.722,42.66) ; v1(67.437,65.532) 68.047,64.922 U7.16@68.961,64.922 ; v1(74.168,59.436) U8.16@75.971,59.436 ; R76.2@78.629,28.194 78.629,24.654 75.692,21.717 BUZZER2.1@75.692,19.812 77.978,17.526 85.344,17.526 90.551,22.733 90.551,26.924 92.075,28.448 R73.2@95.012,28.448 ; 26.352,21.018 27.211,20.16 D1.1@27.211,18.669
XTAL1: C1.1 C7.1 U1.16 X1.2 X2.3 | length 24
  Bottom Layer w0.2: C7.1@33.02,51.673 35.118,51.673 X2.3@35.222,51.777 35.222,53.002 35.814,53.594 41.021,53.594 41.402,53.213 41.402,50.673 41.767,50.308 C1.1@42.799,50.308 42.799,47.772 X1.2@42.779,47.752 43.815,47.752 46.756,44.811 U1.16@46.756,42.731
XTAL2: C2.1 C8.1 U1.15 X1.1 X2.1 | length 17.3
  Bottom Layer w0.2: X2.1@37.422,50.077 37.422,47.779 C8.1@37.449,47.752 ; C8.1@37.449,47.752 X1.1@40.279,47.752 ; C2.1@40.259,50.308 40.279,50.288 X1.1@40.279,47.752 ; U1.15@46.256,42.731 46.256,43.759 44.563,45.452 41.035,45.452 40.279,46.208 X1.1@40.279,47.752
pads on no net: U1.1 U1.4 U1.10 U1.11 U1.12 U1.13 U1.18 U1.25 U1.31 U1.42 U1.48 U2.9 U2.10 U2.13 U3.9 U3.10 U3.13 U4.9 U4.10 U4.13 U5.9 U5.10 U5.13 U6.9 U6.10 U6.13 U7.9 U7.10 U7.13 U8.9 U8.10 U8.13 U9.9 U9.10 U9.13 U10.6 U10.7 U10.9 U10.10 U10.13 USB1.2 USB1.3 USB1.4

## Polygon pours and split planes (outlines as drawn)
GND on Top Layer "GND_L01_P001" (solid, remove dead copper, pour order 1): -0.127,0 -0.127,79.883 0,80.01 99.949,80.01 99.949,0
GND on Bottom Layer "GND_L02_P002" (solid, remove dead copper, pour order 2): 99.949,80.01 99.949,0 0,0 0,80.01 0.127,80.137

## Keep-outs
Keep-Out Layer:
  the board outline again, w0.1

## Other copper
Top Layer:
  region net VCC_5V: 36.703,15.875 38.354,15.875 37.964,15.485 37.964,15

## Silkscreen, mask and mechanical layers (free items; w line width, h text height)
Bottom Overlay:
  text "GND" at 7.139,36.93 h0.8
  text "P3.1" at 7.393,34.39 h0.8
  text "P3.0" at 7.774,31.723 h0.8
  text "VCC_5V" at 9.298,29.189 h0.8
  text "STC12C5-LED-Heart-shaped lamp" at 91.313,3.949 h1.5
  text "V0.1-2023-07-25" at 91.185,2.43 h1.5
